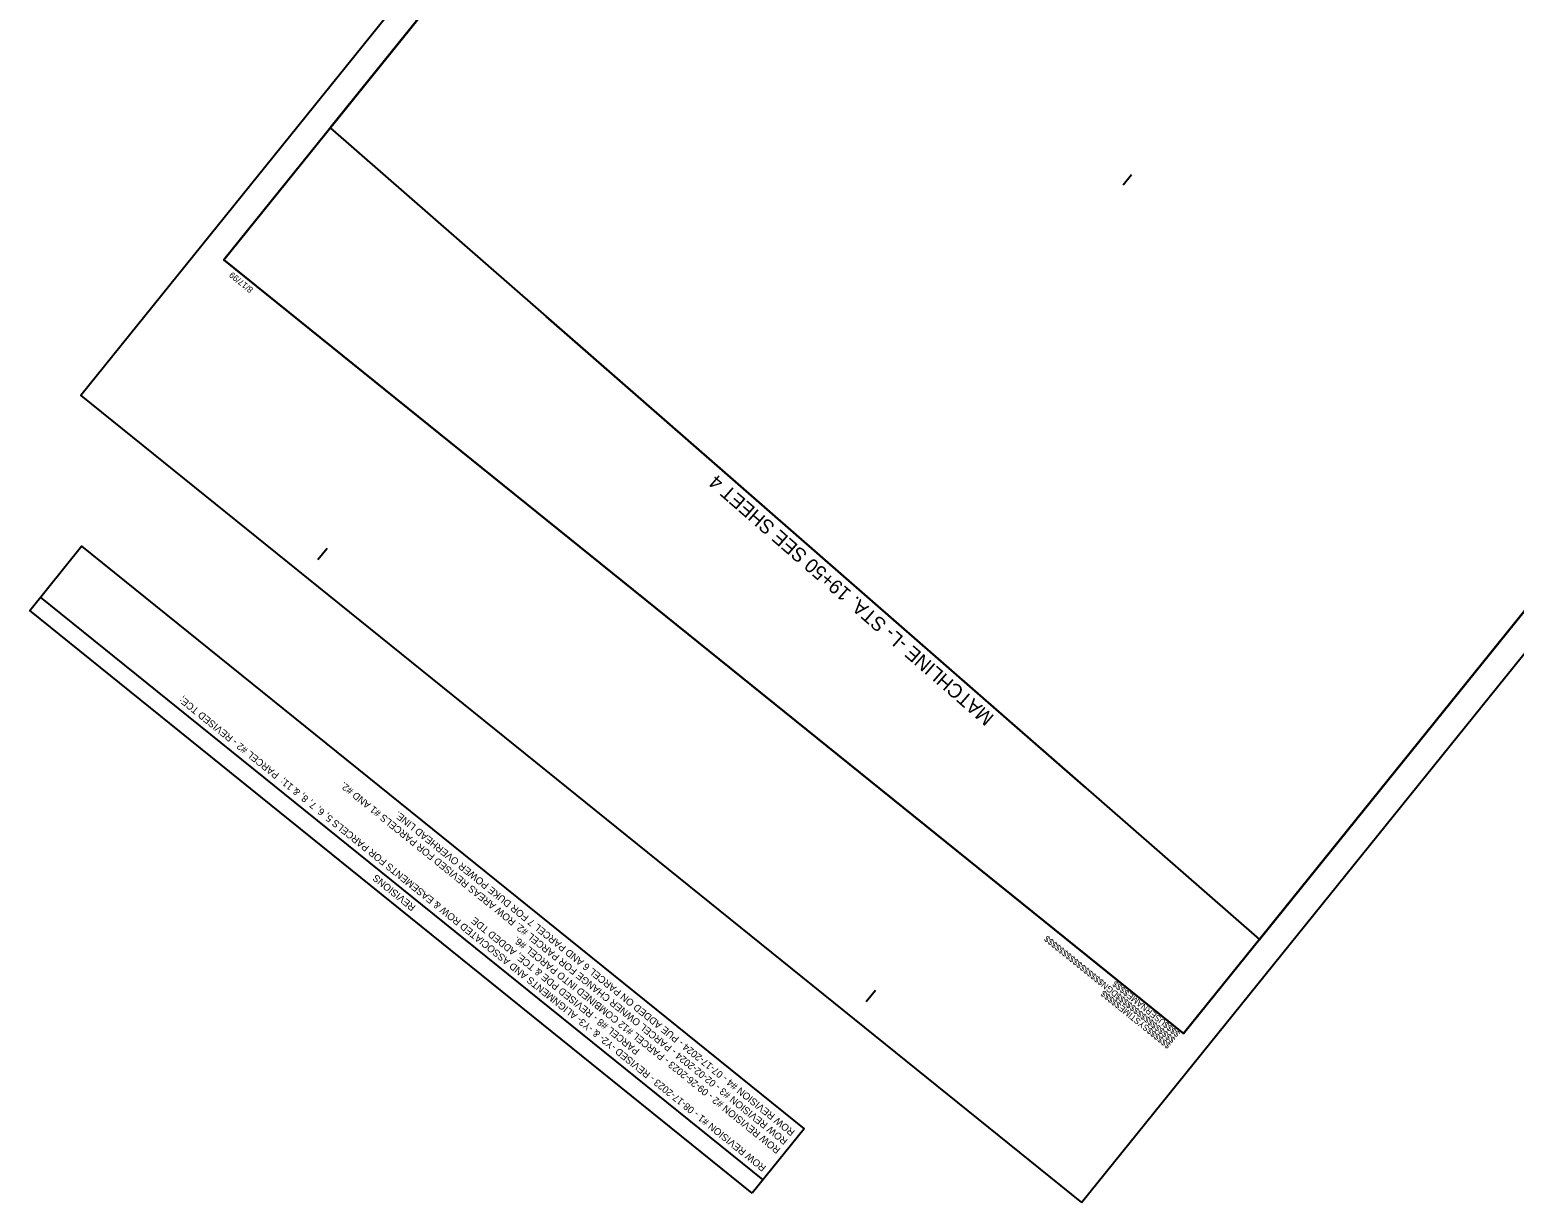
# Model space of a CAD drawing. Extents: x 1487832 to 1490056, y 498345 to 500343.
# Drawn here: x 1487832 to 1489096, y 498345 to 499344 of the extents above; entities that cross this region are included whole.
import ezdxf

# ---------------------------------------------------------------- set-up
doc = ezdxf.new("R2010")
doc.units = 0
for name, color, linetype in [('Matchline', 7, 'Continuous'), ('Matchline Text', 7, 'Continuous'), ('Scratch_Level_3', 7, 'Continuous'), ('Scratch_Level_9', 7, 'Continuous'), ('Sheet Block Revision CELL', 7, 'Continuous'), ('Sheet Clip Boundary CELL', 7, 'Continuous'), ('Sheet Plan CELL', 7, 'Continuous'), ('Sheet Plot Border Outside CELL', 7, 'Continuous')]:
    doc.layers.add(name, color=color, linetype=linetype)

msp = doc.modelspace()

# ---------------------------------------------------------------- linework, layer by layer
at = {"layer": 'Matchline'}
msp.add_line((1488730.9, 498698.6), (1488271.7, 499099.8), dxfattribs=at)
at = {"layer": 'Scratch_Level_3'}
msp.add_line((1488770.3, 499220.5), (1488763.2, 499211.8), dxfattribs=at)
at = {"layer": 'Sheet Block Revision CELL'}
msp.add_line((1488456.4, 498364.6), (1487840.9, 498860.9), dxfattribs=at)
msp.add_lwpolyline([(1488447.2, 498353.2), (1487831.8, 498849.6), (1487875.9, 498904.3), (1488491.3, 498408)], close=True, dxfattribs=at)
at = {"layer": 'Sheet Clip Boundary CELL'}
msp.add_lwpolyline([(1488948.4, 500051.2), (1488813.3, 500160.1), (1488087.8, 499260.5), (1488879.1, 498569.1), (1489756.2, 499656.7), (1489073.9, 500206.9)], close=True, dxfattribs=at)
at = {"layer": 'Sheet Plan CELL'}
for p, q in [((1487997.2, 499148.2), (1487997.2, 499148.2)), ((1488077.2, 498892.9), (1488085, 498902.7)), ((1488544.3, 498516.3), (1488552.1, 498526)), ((1488814.5, 498489), (1488814.5, 498489))]:
    msp.add_line(p, q, dxfattribs=at)
for points in [[(1488938.9, 500315.8), (1487997.2, 499148.2), (1488814.5, 498489), (1489756.2, 499656.7)], [(1488814.5, 498489), (1487997.2, 499148.1), (1488813.3, 500160.1), (1488930.1, 500065.9), (1489055.7, 500221.6), (1489756.2, 499656.7)]]:
    msp.add_lwpolyline(points, close=True, dxfattribs=at)
at = {"layer": 'Sheet Plot Border Outside CELL'}
msp.add_lwpolyline([(1488727.6, 498345.3), (1489784.4, 499655.8), (1488932, 500343.2), (1487875.2, 499032.7)], close=True, dxfattribs=at)

# ---------------------------------------------------------------- texts
at = {"layer": 'Matchline Text'}
msp.add_text('MATCHLINE -L- STA. 19+50 SEE SHEET 4', height=12, rotation=138.9276, dxfattribs=at).set_placement((1488653.9, 498759.4))
at = {"layer": 'Scratch_Level_9'}
for s, p in [('$$$$$$$$$$$$$$$$DGN$$$$$$$$$$$$$$$$', (1488807.9, 498484.6)), ('$$$$USERNAME$$$$', (1488812, 498489.7)), ('$$$$$$SYSTIME$$$$$', (1488804.1, 498479.8))]:
    msp.add_text(s, height=5.25, rotation=141.1157, dxfattribs=at).set_placement(p)
at = {"layer": 'Sheet Block Revision CELL'}
for s, p in [('ROW REVISION #1 - 08-17-2023 - REVISED -Y2- & -Y3- ALIGNMENTS AND ASSOCIATED ROW & EASEMENTS FOR PARCELS 5, 6, 7, 8, & 11;  PARCEL #2 - REVISED TCE;', (1488459.5, 498375.7)), ('ROW REVISION #3 - 02-02-2024 - PARCEL OWNER CHANGE FOR PARCEL #2. ROW AREAS REVISED FOR PARCELS #1 AND #2.', (1488477.9, 498398.5)), ('ROW REVISION #4 - 07-17-2024 - PUE ADDED ON PARCEL 6 AND PARCEL 7 FOR DUKE POWER OVERHEAD LINE.', (1488484, 498406)), ('REVISIONS', (1488161, 498597.6)), (' PARCEL #8 - REVISED PDE & TCE, ADDED TDE', (1488353.5, 498473.7)), ('ROW REVISION #2 - 09-26-2023 - PARCEL #12 COMBINED INTO PARCEL #6.', (1488471.7, 498390.9))]:
    msp.add_text(s, height=6, rotation=141.1156, dxfattribs=at).set_placement(p)
at = {"layer": 'Sheet Plan CELL'}
msp.add_text('8/17/99', height=5.25, rotation=141.1157, dxfattribs=at).set_placement((1488022.6, 499123.6))

doc.saveas('drawing.dxf')
